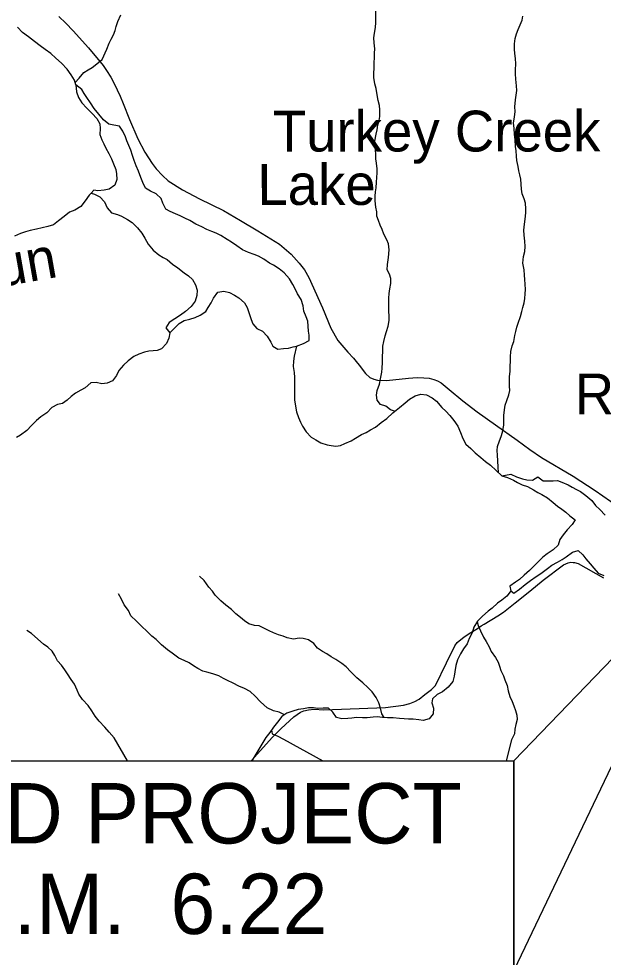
# Model space of a CAD drawing. Extents: x 0 to 34, y 0 to 22.
# Drawn here: x 6.061 to 7.417, y 15.178 to 17.355 of the extents above; entities that cross this region are included whole.
import ezdxf

# ---------------------------------------------------------------- set-up
doc = ezdxf.new("R2010")
doc.units = 0
for name, color, linetype in [('GM_X_Major_River', 7, 'Continuous'), ('GM_X_Minor_Lake', 7, 'Continuous'), ('GM_X_Minor_Lake_Text', 7, 'Continuous'), ('GM_X_Minor_River', 7, 'Continuous'), ('GM_X_Minor_River_Text', 7, 'Continuous'), ('GM_X_State_Route', 7, 'Continuous'), ('GM_X_Township_Road', 7, 'Continuous'), ('SH_Text', 7, 'Continuous')]:
    doc.layers.add(name, color=color, linetype=linetype)

msp = doc.modelspace()

# ---------------------------------------------------------------- linework, layer by layer
at = {"layer": 'GM_X_Major_River'}
msp.add_lwpolyline([(6.7055, 16.5956), (6.7004, 16.5724), (6.6989, 16.5606), (6.6981, 16.5484), (6.7005, 16.5344), (6.7012, 16.5226), (6.7013, 16.5108), (6.7009, 16.4968), (6.7009, 16.4808), (6.7013, 16.4709), (6.7029, 16.4561), (6.7055, 16.4432), (6.7101, 16.4303), (6.7151, 16.4193), (6.7197, 16.4098), (6.7284, 16.3969), (6.7395, 16.3848), (6.7506, 16.378), (6.7624, 16.3712), (6.7764, 16.3666), (6.786, 16.3648), (6.797, 16.3636), (6.8076, 16.3652), (6.8179, 16.3694), (6.8324, 16.3763), (6.8426, 16.382), (6.8567, 16.3904), (6.8673, 16.3953), (6.8776, 16.4011), (6.8886, 16.4079), (6.9019, 16.4182), (6.9152, 16.4281), (6.9289, 16.4411), (6.9445, 16.4536), (6.9578, 16.4643), (6.9677, 16.4727), (6.9806, 16.4807), (6.9939, 16.4845), (7.0068, 16.483), (7.0205, 16.4755), (7.0301, 16.4683), (7.0426, 16.4535), (7.0522, 16.4451), (7.0613, 16.4345), (7.0709, 16.4228), (7.0796, 16.4099), (7.0857, 16.3954), (7.0915, 16.3814), (7.0987, 16.3685), (7.1098, 16.3579), (7.1201, 16.3484), (7.1334, 16.3374), (7.1437, 16.3279), (7.1559, 16.3192), (7.1822, 16.295)], dxfattribs=at)
at = {"layer": 'GM_X_Minor_Lake'}
for points in [[(6.1935, 17.202), (6.1956, 17.1857), (6.2002, 17.1723), (6.2079, 17.1598), (6.2189, 17.1477), (6.2315, 17.1352), (6.2425, 17.1238), (6.2494, 17.1116), (6.2502, 17.1002), (6.2498, 17.0866), (6.2544, 17.0744), (6.259, 17.0649), (6.2636, 17.0551), (6.2701, 17.0422), (6.2766, 17.03), (6.2811, 17.0183), (6.2865, 17.005), (6.288, 16.9955), (6.2892, 16.9822), (6.2839, 16.9692), (6.271, 16.9597), (6.2592, 16.9574), (6.2451, 16.9562), (6.2352, 16.9574), (6.229, 16.9504), (6.2367, 16.9482), (6.2493, 16.9422), (6.26, 16.9304), (6.2665, 16.9164), (6.2764, 16.9046), (6.2901, 16.9009), (6.3, 16.8971), (6.3133, 16.8891), (6.3247, 16.8827), (6.3369, 16.8702), (6.3472, 16.8573), (6.3537, 16.8459), (6.3613, 16.8323), (6.3728, 16.8182), (6.3861, 16.8076), (6.396, 16.8016), (6.4059, 16.7963), (6.4177, 16.786), (6.4303, 16.7769), (6.4448, 16.7656), (6.4547, 16.7584), (6.4646, 16.7504), (6.4711, 16.7379), (6.4749, 16.7258), (6.4742, 16.7128)], [(6.7055, 16.5956), (6.7217, 16.6017), (6.735, 16.6086), (6.7349, 16.6207), (6.7334, 16.6306), (6.7326, 16.642), (6.7318, 16.6534), (6.728, 16.6633), (6.7223, 16.6765), (6.7211, 16.6895), (6.7162, 16.7039), (6.7082, 16.7168), (6.7024, 16.7289), (6.6971, 16.7384), (6.6891, 16.7521), (6.6769, 16.7653), (6.6651, 16.7748), (6.6525, 16.7831), (6.6426, 16.7884), (6.63, 16.7975), (6.6171, 16.8047), (6.6072, 16.8081), (6.5946, 16.8126), (6.5805, 16.8187), (6.5672, 16.8282), (6.5546, 16.8365), (6.5447, 16.8429), (6.5299, 16.852), (6.5196, 16.8573), (6.5089, 16.8618), (6.4975, 16.8664), (6.4857, 16.8721), (6.472, 16.8789), (6.4579, 16.8868), (6.4469, 16.8925), (6.4358, 16.8978), (6.4248, 16.9027), (6.4122, 16.908), (6.4027, 16.9137), (6.3954, 16.9269), (6.3916, 16.9383), (6.3802, 16.9486), (6.3672, 16.955), (6.355, 16.9622), (6.3489, 16.9755), (6.3447, 16.9865), (6.339, 17.0013), (6.3337, 17.0142), (6.3287, 17.0263), (6.3249, 17.0377), (6.321, 17.0503), (6.3165, 17.0613), (6.3122, 17.0719), (6.3088, 17.0814), (6.3031, 17.0943), (6.2947, 17.1057), (6.2821, 17.1083), (6.27, 17.1105), (6.2578, 17.1208), (6.2364, 17.1466), (6.2276, 17.1598), (6.2193, 17.1724), (6.2131, 17.1818), (6.2074, 17.1913), (6.1935, 17.202)], [(6.4742, 16.7128), (6.4704, 16.6999), (6.4616, 16.6877), (6.4483, 16.6759), (6.4369, 16.6672), (6.4103, 16.6504), (6.4027, 16.6382), (6.4119, 16.6268), (6.4332, 16.6482), (6.4453, 16.655), (6.4579, 16.6585), (6.4704, 16.6623), (6.4822, 16.6676), (6.4951, 16.6756), (6.5008, 16.6852), (6.5073, 16.6962), (6.5134, 16.7072), (6.5232, 16.7205), (6.5369, 16.7229), (6.5499, 16.7198), (6.5617, 16.7138), (6.5719, 16.7074), (6.5849, 16.696), (6.5914, 16.685), (6.596, 16.6717), (6.6006, 16.6573), (6.6044, 16.6474), (6.6135, 16.6364), (6.6269, 16.6307), (6.6379, 16.6186), (6.6459, 16.6049), (6.6509, 16.5955), (6.6623, 16.5886), (6.6753, 16.5898), (6.6874, 16.591), (6.6981, 16.594), (6.7055, 16.5956)], [(7.1822, 16.295), (7.2027, 16.2984), (7.2156, 16.2928), (7.2297, 16.2879), (7.24, 16.2856), (7.2529, 16.2849), (7.2655, 16.2921), (7.2781, 16.2834), (7.2876, 16.2831), (7.3009, 16.2835), (7.3112, 16.2839), (7.3214, 16.2797), (7.3355, 16.274), (7.3451, 16.2687), (7.355, 16.2634), (7.3645, 16.2581), (7.3767, 16.2491), (7.3908, 16.2377), (7.3995, 16.2263), (7.4091, 16.2168), (7.4213, 16.2039)], [(7.1822, 16.295), (7.1947, 16.2908), (7.2088, 16.2844), (7.2183, 16.2795), (7.2294, 16.2738), (7.2416, 16.2697), (7.2556, 16.2625), (7.2652, 16.2564), (7.2747, 16.2515), (7.2876, 16.2439), (7.3006, 16.2326), (7.3113, 16.2242), (7.3208, 16.2178), (7.3303, 16.2102), (7.3398, 16.2022), (7.352, 16.1928), (7.3448, 16.1821), (7.3338, 16.1696), (7.3243, 16.1578), (7.3163, 16.1471), (7.3125, 16.1338), (7.3011, 16.1228), (7.2867, 16.1136), (7.2772, 16.106), (7.2677, 16.0972), (7.2559, 16.085), (7.2464, 16.0751), (7.2339, 16.0641), (7.2229, 16.0542), (7.2134, 16.0481), (7.2001, 16.0386), (7.2031, 16.0281), (7.2096, 16.0226), (7.2229, 16.0322), (7.2362, 16.0424), (7.2484, 16.052), (7.2613, 16.0611), (7.2723, 16.068), (7.2875, 16.0802), (7.2982, 16.0874), (7.3111, 16.0947), (7.3217, 16.1008), (7.3312, 16.1065), (7.3457, 16.1175), (7.3586, 16.1217), (7.37, 16.1119), (7.3769, 16.1024), (7.3864, 16.0906), (7.3952, 16.0808), (7.4055, 16.069), (7.4184, 16.0634)]]:
    msp.add_lwpolyline(points, dxfattribs=at)
at = {"layer": 'GM_X_Minor_River'}
for points in [[(6.9332, 16.4446), (6.9236, 16.4476), (6.913, 16.4564), (6.9001, 16.4606), (6.8929, 16.4706), (6.8911, 16.482), (6.893, 16.493), (6.8985, 16.5077), (6.9008, 16.5199), (6.9036, 16.5351), (6.9044, 16.5449), (6.9052, 16.5574), (6.9053, 16.5711), (6.9058, 16.5836), (6.9059, 16.5958), (6.9078, 16.6064), (6.9109, 16.6193), (6.914, 16.6295), (6.9179, 16.6417), (6.9203, 16.655), (6.9207, 16.6644), (6.92, 16.6777), (6.9197, 16.6907), (6.9198, 16.7066), (6.9203, 16.7176), (6.9219, 16.7286), (6.9242, 16.7408), (6.9243, 16.7525), (6.9213, 16.7624), (6.9161, 16.7723), (6.9165, 16.7852), (6.9193, 16.8012), (6.9206, 16.819), (6.9191, 16.8331), (6.915, 16.8426), (6.9079, 16.8555), (6.9045, 16.8662), (6.9, 16.8765), (6.8955, 16.8871), (6.8921, 16.8974), (6.8918, 16.9069), (6.89, 16.9183), (6.8882, 16.9327), (6.8879, 16.9437), (6.8887, 16.9532), (6.8907, 16.9631), (6.8911, 16.976), (6.8923, 16.987), (6.8928, 16.9973), (6.8925, 17.0068), (6.891, 17.0201), (6.8899, 17.0299), (6.8896, 17.0402), (6.8889, 17.0512), (6.8882, 17.0607), (6.8875, 17.071), (6.8903, 17.0873), (6.8926, 17.0975), (6.8942, 17.1093), (6.8973, 17.1187), (6.8989, 17.1286), (6.899, 17.1434), (6.8983, 17.1541), (6.895, 17.1655), (6.8924, 17.1784), (6.8906, 17.1936), (6.8872, 17.2042), (6.885, 17.2187), (6.8847, 17.2286), (6.8855, 17.2403), (6.886, 17.254), (6.8865, 17.2635), (6.8869, 17.2749), (6.8873, 17.2851), (6.8855, 17.2992), (6.8852, 17.311), (6.8864, 17.3216), (6.8888, 17.3349), (6.8896, 17.3463), (6.8898, 17.3804)], [(6.192, 17.2071), (6.2015, 17.2176), (6.2122, 17.2301), (6.2222, 17.2368), (6.2317, 17.2421), (6.2428, 17.2504), (6.2546, 17.2606), (6.2654, 17.2844), (6.2708, 17.2981), (6.2758, 17.3079), (6.2812, 17.3178), (6.2851, 17.3276), (6.287, 17.3371), (6.2909, 17.3489), (6.2978, 17.3644)], [(7.1738, 16.3027), (7.1736, 16.3152), (7.1726, 16.3292), (7.1715, 16.3429), (7.1712, 16.3532), (7.172, 16.363), (7.1763, 16.3759), (7.1801, 16.3858), (7.1833, 16.3964), (7.1868, 16.4123), (7.1869, 16.4344), (7.1878, 16.4476), (7.1893, 16.4586), (7.1932, 16.4693), (7.1982, 16.4825), (7.2002, 16.4928), (7.1999, 16.5026), (7.1996, 16.5121), (7.2, 16.5243), (7.2009, 16.5372), (7.2013, 16.5501), (7.2018, 16.56), (7.2018, 16.5706), (7.2027, 16.5831), (7.2062, 16.5964), (7.2097, 16.6066), (7.2124, 16.6203), (7.2144, 16.6298), (7.2163, 16.6396), (7.2194, 16.6491), (7.2252, 16.6643), (7.228, 16.676), (7.2303, 16.6855), (7.2338, 16.6957), (7.2354, 16.706), (7.2362, 16.7166), (7.2366, 16.7272), (7.2363, 16.739), (7.2353, 16.7504), (7.2342, 16.7603), (7.2339, 16.7724), (7.2309, 16.7884), (7.2322, 16.8036), (7.2349, 16.8153), (7.2361, 16.8267), (7.2354, 16.8389), (7.234, 16.8529), (7.2333, 16.8647), (7.2346, 16.8788), (7.2358, 16.8905), (7.2378, 16.9046), (7.2374, 16.9144), (7.2364, 16.927), (7.2334, 16.9376), (7.2293, 16.949), (7.2278, 16.9597), (7.2257, 16.9832), (7.2239, 16.9927), (7.2216, 17.0023), (7.2194, 17.0121), (7.2168, 17.0262), (7.2158, 17.0361), (7.2151, 17.049), (7.2136, 17.0585), (7.2126, 17.0741), (7.2111, 17.087), (7.2105, 17.1003), (7.209, 17.114), (7.211, 17.1265), (7.2126, 17.1401), (7.2119, 17.1504), (7.2132, 17.1667), (7.2151, 17.1781), (7.2163, 17.1884), (7.2156, 17.1997), (7.2146, 17.2149), (7.2135, 17.2271), (7.2136, 17.2366), (7.2144, 17.2503), (7.2134, 17.2632), (7.2123, 17.2742), (7.2112, 17.2848), (7.2113, 17.2966), (7.2129, 17.3095), (7.216, 17.3197), (7.2199, 17.33), (7.2245, 17.341), (7.2288, 17.3516), (7.2303, 17.3614)], [(6.1935, 17.202), (6.1905, 17.2127), (6.1833, 17.2249), (6.1739, 17.2383), (6.1607, 17.2524), (6.1474, 17.2638), (6.1357, 17.2745), (6.1229, 17.2834), (6.1111, 17.2922), (6.0975, 17.3025), (6.0839, 17.3132), (6.0699, 17.3231), (6.0582, 17.3357)], [(6.229, 16.9504), (6.2249, 16.9456), (6.2153, 16.9327), (6.205, 16.9199), (6.1916, 16.9112), (6.179, 16.9067), (6.1664, 16.8962), (6.1534, 16.886), (6.1416, 16.8773), (6.129, 16.8728), (6.1153, 16.8702), (6.1024, 16.8673), (6.0879, 16.8636), (6.0769, 16.861), (6.0651, 16.8572), (6.0514, 16.8509)], [(6.4119, 16.6268), (6.4091, 16.6142), (6.4037, 16.6017), (6.3922, 16.5896), (6.3827, 16.5858), (6.3728, 16.5851), (6.3633, 16.584), (6.353, 16.5814), (6.3397, 16.577), (6.3283, 16.5717), (6.3149, 16.5619), (6.3042, 16.5513), (6.2935, 16.5389), (6.2881, 16.5279), (6.2785, 16.515), (6.2667, 16.5098), (6.2541, 16.5083), (6.2408, 16.5111), (6.2287, 16.5104), (6.2157, 16.499), (6.2057, 16.4934), (6.1928, 16.4863), (6.1832, 16.4787), (6.1737, 16.47), (6.163, 16.4629), (6.1516, 16.4603), (6.1382, 16.4532), (6.1267, 16.4411), (6.1122, 16.4313), (6.1027, 16.423), (6.0912, 16.4113), (6.0797, 16.3996), (6.0656, 16.389), (6.056, 16.3838)], [(6.9092, 15.734), (6.9039, 15.7425), (6.9002, 15.7562), (6.8969, 15.768), (6.8901, 15.7806), (6.8811, 15.7935), (6.8712, 15.8035), (6.8591, 15.8146), (6.8459, 15.826), (6.8316, 15.8405), (6.8206, 15.852), (6.8104, 15.8596), (6.7968, 15.8688), (6.7858, 15.875), (6.7759, 15.8815), (6.7657, 15.8876), (6.7543, 15.8953), (6.7457, 15.9056), (6.7336, 15.914), (6.7214, 15.9175), (6.7119, 15.9183), (6.699, 15.9161), (6.6842, 15.9188), (6.6747, 15.9227), (6.6637, 15.9258), (6.6519, 15.9308), (6.6421, 15.935), (6.6193, 15.9465), (6.6079, 15.9474), (6.595, 15.9512), (6.5852, 15.9585), (6.5754, 15.9665), (6.5648, 15.9746), (6.555, 15.9849), (6.5417, 15.9944), (6.53, 16.0048), (6.5171, 16.0177), (6.5104, 16.0273), (6.5024, 16.0368), (6.4915, 16.0517), (6.4809, 16.062)], [(7.2031, 16.0281), (7.1989, 16.0225), (7.1933, 16.0155), (7.182, 16.006), (7.172, 15.9996), (7.1598, 15.9879), (7.1502, 15.9808), (7.1369, 15.9694), (7.1254, 15.9574), (7.1173, 15.9441), (7.1127, 15.9305), (7.1061, 15.9172), (7.1015, 15.9047), (7.0927, 15.8934), (7.0861, 15.8816), (7.0792, 15.8676), (7.0753, 15.8551), (7.073, 15.8403), (7.071, 15.8301), (7.0682, 15.8176), (7.0571, 15.8047), (7.0445, 15.7934), (7.0316, 15.7874), (7.0209, 15.7776), (7.0193, 15.7681), (7.023, 15.7555), (7.0225, 15.743), (7.0137, 15.7313), (6.9993, 15.7276), (6.9894, 15.7284), (6.9761, 15.7307), (6.9654, 15.7304), (6.9552, 15.7309), (6.9445, 15.7317), (6.9297, 15.7333), (6.9164, 15.7337), (6.905, 15.7342), (6.8929, 15.7354), (6.8834, 15.7351), (6.8693, 15.7336), (6.859, 15.7333), (6.845, 15.7341), (6.8343, 15.7327), (6.8244, 15.7316), (6.8111, 15.7309), (6.7982, 15.734), (6.7899, 15.7466), (6.7801, 15.7558), (6.7675, 15.7555), (6.7546, 15.7551), (6.7451, 15.7563), (6.7337, 15.7564), (6.7219, 15.7546), (6.7094, 15.7524), (6.6972, 15.749), (6.6835, 15.7442), (6.6716, 15.7362), (6.6613, 15.723), (6.6521, 15.7117), (6.644, 15.6996), (6.6348, 15.6875), (6.6023, 15.6335)], [(6.678, 15.7405), (6.6652, 15.7462), (6.6523, 15.7493), (6.6372, 15.7566), (6.622, 15.7703), (6.61, 15.7833), (6.5979, 15.7944), (6.585, 15.8013), (6.5721, 15.8071), (6.5588, 15.814), (6.5459, 15.8197), (6.5361, 15.8243), (6.5255, 15.8305), (6.5118, 15.8355), (6.4978, 15.839), (6.4883, 15.8413), (6.4765, 15.8478), (6.4667, 15.854), (6.4569, 15.8609), (6.4447, 15.8663), (6.4326, 15.872), (6.4171, 15.8831), (6.4061, 15.8908), (6.3921, 15.9026), (6.3797, 15.9152), (6.3698, 15.9225), (6.3585, 15.9343), (6.3468, 15.945), (6.3347, 15.958), (6.3215, 15.9702), (6.3158, 15.9824), (6.3056, 15.9958), (6.3, 16.0083), (6.2929, 16.0209)], [(6.3136, 15.6335), (6.2828, 15.6868), (6.2711, 15.6998), (6.2613, 15.712), (6.2481, 15.7253), (6.2383, 15.7375), (6.2307, 15.7494), (6.2221, 15.7619), (6.2092, 15.7761), (6.201, 15.7883), (6.1968, 15.7978), (6.1908, 15.8115), (6.1829, 15.8225), (6.1743, 15.8355), (6.1682, 15.845), (6.1603, 15.8553), (6.1516, 15.866), (6.1449, 15.8782), (6.1389, 15.8881), (6.129, 15.8973), (6.1188, 15.9042), (6.1056, 15.916), (6.0912, 15.929), (6.0799, 15.9359)], [(7.1246, 15.9561), (7.1268, 15.9479), (7.1321, 15.9349), (7.1396, 15.9208), (7.1456, 15.9105), (7.1528, 15.8983), (7.1573, 15.8873), (7.1674, 15.8736), (7.1735, 15.8629), (7.1764, 15.8534), (7.1798, 15.8431), (7.1854, 15.831), (7.1888, 15.8214), (7.1944, 15.8085), (7.1966, 15.796), (7.2007, 15.7826), (7.206, 15.7712), (7.2101, 15.7609), (7.2138, 15.7503), (7.2168, 15.7393), (7.2175, 15.7294), (7.2147, 15.718), (7.212, 15.707), (7.2116, 15.696), (7.2046, 15.682), (7.1918, 15.6335)], [(6.6479, 15.7054), (6.6493, 15.6965), (6.6622, 15.6907), (6.6755, 15.6838), (6.7666, 15.6335)]]:
    msp.add_lwpolyline(points, dxfattribs=at)
at = {"layer": 'GM_X_State_Route'}
msp.add_lwpolyline([(6.1545, 17.3603), (6.1708, 17.345), (6.1874, 17.327), (6.2229, 17.2875), (6.2569, 17.2467), (6.2647, 17.2348), (6.2746, 17.2194), (6.2826, 17.2052), (6.2966, 17.1755), (6.3036, 17.1581), (6.3181, 17.1213), (6.3376, 17.0766), (6.3541, 17.0456), (6.3707, 17.0194), (6.3797, 17.0072), (6.3946, 16.9917), (6.4083, 16.9792), (6.4412, 16.9579), (6.4808, 16.9376), (6.5359, 16.9106), (6.5754, 16.8872), (6.6162, 16.8633), (6.6659, 16.8321), (6.6935, 16.8087), (6.7121, 16.7884), (6.7242, 16.7723), (6.7342, 16.7548), (6.766, 16.6847), (6.7852, 16.6373), (6.8014, 16.6086), (6.8248, 16.5819), (6.8375, 16.5681), (6.844, 16.56), (6.851, 16.5511), (6.8653, 16.5321), (6.876, 16.5232), (6.8846, 16.5192), (6.8934, 16.5169), (6.9146, 16.5157), (6.9656, 16.5211), (6.9854, 16.5227), (7.0012, 16.5223), (7.013, 16.5211), (7.0242, 16.5184), (7.0329, 16.5148), (7.0409, 16.5103), (7.0596, 16.4953), (7.0918, 16.4685), (7.125, 16.4432), (7.1669, 16.4132), (7.2172, 16.3773), (7.2466, 16.3557), (7.2742, 16.3376), (7.3472, 16.294), (7.3982, 16.261), (7.4515, 16.2235)], dxfattribs=at)
at = {"layer": 'GM_X_Township_Road'}
for points in [[(7.1103, 15.9313), (7.1255, 15.9408), (7.1339, 15.9465), (7.1412, 15.9509), (7.1728, 15.9704), (7.1858, 15.9789), (7.213, 16.0005), (7.2469, 16.0271), (7.2778, 16.0529), (7.3249, 16.088), (7.336, 16.0932), (7.3422, 16.0944), (7.3471, 16.094), (7.3507, 16.0937), (7.3592, 16.0914), (7.4175, 16.0584)], [(6.6002, 15.6335), (6.6501, 15.6882), (6.6591, 15.698), (6.6702, 15.7087), (6.6993, 15.7359), (6.7146, 15.7469), (6.7224, 15.7499), (6.7331, 15.7522), (6.7466, 15.7532), (6.7692, 15.7522), (6.9117, 15.7572), (6.9538, 15.7627), (6.9685, 15.7666), (6.98, 15.7715), (6.9905, 15.7771), (7.0034, 15.7873), (7.0184, 15.799), (7.0281, 15.8088), (7.0534, 15.8611), (7.073, 15.9007), (7.0785, 15.9085), (7.0944, 15.9213), (7.1103, 15.9313)]]:
    msp.add_lwpolyline(points, dxfattribs=at)
at = {"layer": 'SH_Text'}
for points in [[(7.2097, 15.6335), (7.6704, 16.1119), (7.2097, 15.147)], [(5.7139, 15.6335), (7.2097, 15.6335), (7.2097, 15.147), (5.7139, 15.147)]]:
    msp.add_lwpolyline(points, close=True, dxfattribs=at)

# ---------------------------------------------------------------- texts
at = {"layer": 'GM_X_Minor_Lake_Text'}
for s, height, rotation, p in [('Turkey Creek', 0.094699, 0.0044, (6.6506, 17.0471)), ('Lake', 0.0947, 0.0045, (6.6148, 16.9232)), ('Roosevelt', 0.0947, 0.0024, (7.351, 16.4372))]:
    msp.add_text(s, height=height, rotation=rotation, dxfattribs=at).set_placement(p)
at = {"layer": 'GM_X_Minor_River_Text'}
msp.add_text('Run', height=0.0947, rotation=10.002, dxfattribs=at).set_placement((5.9262, 16.7162))
at = {"layer": 'SH_Text'}
for s, p in [('END PROJECT', (5.7682, 15.442)), ('S.L.M.  6.22', (5.7682, 15.232))]:
    msp.add_text(s, height=0.14, dxfattribs=at).set_placement(p)

doc.saveas('drawing.dxf')
